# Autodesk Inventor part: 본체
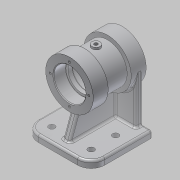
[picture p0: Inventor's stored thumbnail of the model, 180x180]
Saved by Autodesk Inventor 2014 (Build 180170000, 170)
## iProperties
Created: 2020-06
Part Number: 본체
Material: 알루미늄 6061
Document SubType Name: 판금
Designer: NET
Density: 2.71 g/cm^3
Appearance: 알루미늄 - 평지
Sheet Metal Rule: 기본값
Mass: 729.164 g
Surface Area: 648.266 cm^2
Volume: 269.064 cm^3
Author: NET
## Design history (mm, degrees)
sketch "스케치1"
  geometry: C1 r 29 at (0, 0); 1 further point
  constraints: 1 centre point, 1 coincident
  dimensions: "d0" = 58 diameter of C1
extrude "돌출1" new body sketch "스케치1" stored distance "d1" = 78; taper "d2" = 0 deg
node "작업 평면1"
sketch "스케치2"
  geometry: 1 further point
sketch "스케치3"
  geometry: L1 (-49, -51)-(49, -51); L2 (49, -51)-(49, 39); L3 (49, 39)-(-49, 39); L4 (-49, 39)-(-49, -51); L5 (29, 39)-(-29, 39) reference; L6 (-29, -39)-(29, -39) reference; L7 (29, 39)-(-29, 39) reference; 1 further point
  constraints: 8 end point, 2 parallel, 1 horizontal, 1 perpendicular, 1 point on line
  dimensions: "d4" = 49 distance from line of point (0, 0) L4; "d5" = 98 distance of L2.end L3.end; "d6" = 90 distance between parallel lines of L1 L3
extrude "돌출2" join sketch "스케치3" distance "d7" = 10; taper "d8" = 0 deg
sketch "스케치6"
  geometry: L1 (49, 39)-(-49, 39) reference; L2 (-35, 29)-(35, 29); L3 (35, 29)-(35, 39); L4 (35, 39)-(-35, 39); L5 (-35, 39)-(-35, 29); 2 further points
  constraints: 8 end point, 2 midpoint, 2 parallel, 1 horizontal, 1 perpendicular
  dimensions: "d22" = 70 distance between parallel lines of L3 L5; "d23" = 35 distance from line of point (0, 0) L5; "d24" = 10 distance between parallel lines of L2 L4
sketch "스케치7"
  geometry: C1 r 29 at (0, 0) reference; C2 r 35 at (0, 0)
  constraints: 1 centre point, 1 coincident
  dimensions: "d25" = 70 diameter of C2
extrude "돌출4" join sketch "스케치7" distance "d26" = 27; taper "d27" = 0 deg
sketch "스케치8"
  geometry: C1 r 29 at (0, 0) reference; C2 r 35 at (0, 0)
  constraints: 1 centre point, 1 coincident
  dimensions: "d28" = 70 diameter of C2
extrude "돌출5" join sketch "스케치8" distance "d29" = 22; taper "d30" = 0 deg
extrude "돌출6" join sketch "스케치6" stored distance "d31" = 22; taper "d32" = 0 deg
sketch "스케치10"
  geometry: C1 r 35 at (0, 0) reference; C2 r 23.5 at (0, 0)
  constraints: 1 centre point, 1 coincident
  dimensions: "d41" = 47 diameter of C2
extrude "돌출7" cut sketch "스케치10" distance "d42" = 18; taper "d43" = 0 deg
node "작업 평면3"
sketch "스케치19"
  geometry: L1 (49, 39)-(-49, 39) reference; C1 r 4.5 at (29, 5); C2 r 4.5 at (29, -31); C3 r 4.5 at (-29, 5); C4 r 4.5 at (-29, -31); 1 further point
  constraints: 4 centre point, 3 equal radius, 2 vertical alignment, 1 horizontal alignment
  dimensions: "d63" = 36 distance of C2.centre C1.centre; "d64" = 36 distance of C4.centre C3.centre; "d66" = 29 horizontal distance of point (0, 0) C2.centre; "d67" = 70 distance from line of C2.centre L1; "d68" = 58 distance of C4.centre C2.centre; "d69" = 9 diameter of C2
extrude "돌출13" cut sketch "스케치19" stored distance "d70" = 18; taper "d71" = 0 deg
sketch "스케치20"
  geometry: C1 r 23.5 at (0, 0) reference; C2 r 35 at (0, 0) reference; A1 r 28.5 centre (0, 0) between (0, 28.5) and (-28.5, 0); 2 further points
  constraints: 4 point on circle, 2 horizontal alignment, 2 vertical alignment, 1 centre point, 1 coincident
  dimensions: "d72" = 57 diameter of A1
hole "구멍1" sketch "스케치20" at (0, 28.5), (-28.5, 0), (0, -28.5), (28.5, 0) diameter "d73" = 3.242; stored, may be unused: countersink angle "d77" = 90 deg, drill point angle "d79" = 118 deg; dims "d74" = 10, "d75" = 4, "d76" = 2, "d78" = 12
sketch "스케치22"
  geometry: L1 (35, 70)-(35, 0) reference; C1 r 23.5 at (0, 0) reference; C2 r 35 at (0, 0); A1 r 35 centre (0, 0) between (-35, 0) and (35, 0) reference
  constraints: 1 centre point, 1 coincident, 1 tangent
extrude "돌출14" join sketch "스케치22" distance "d80" = 5; taper "d81" = 0 deg
sketch "스케치24"
  geometry: C1 r 35 at (0, 0); A1 r 29 centre (0, 0) between (-29, 0) and (-29, 0) reference
  constraints: 1 centre point, 1 coincident
extrude "돌출15" cut sketch "스케치24" distance "d82" = 5; taper "d83" = 0 deg
sketch "스케치28"
  geometry: C1 r 1.621 at (0, -28.5) reference; C2 r 1.621 at (0, 28.5) reference; C3 r 1.621 at (-28.5, 0) reference; C4 r 1.621 at (28.5, 0) reference; C5 r 23.5 at (0, 0) reference; C6 r 35 at (0, 0) reference; C7 r 35 at (0, 0)
  constraints: 1 centre point, 1 coincident, 1 concentric
extrude "돌출17" cut sketch "스케치28" distance "d87" = 5; taper "d88" = 0 deg
sketch "스케치31"
  geometry: C1 r 23.5 at (0, 0) reference; C2 r 35 at (0, 0) reference; A1 r 28.5 centre (0, 0) between (0, -28.5) and (28.5, 0); 2 further points
  constraints: 4 point on circle, 2 horizontal alignment, 2 vertical alignment, 1 centre point, 1 coincident
  dimensions: "d97" = 57 diameter of A1
hole "구멍2" sketch "스케치31" at (0, -28.5), (28.5, 0), (0, 28.5), (-28.5, 0) diameter "d98" = 3.242; stored, may be unused: countersink angle "d102" = 90 deg, drill point angle "d104" = 118 deg; dims "d99" = 10, "d100" = 4, "d101" = 2, "d103" = 12
node "작업 평면4"
sketch "스케치32"
  geometry: L1 (-23.5, 44)-(23.5, 44) reference; C1 r 6 at (0, 5); 1 further point
  constraints: 1 centre point, 1 vertical alignment
  dimensions: "d106" = 39 distance from line of C1.centre L1; "d107" = 12 diameter of C1
extrude "돌출18" join sketch "스케치32" stored distance "d108" = 5; taper "d109" = 0 deg
sketch "스케치33"
  geometry: C1 r 6 at (0, 0) reference; 1 further point
chamfer "모따기1" distance "d117" = 1; stored, may be unused: second distance "d118" = 2, angle "d119" = 45 deg
fillet "모깎기5" dims "d121" = 20
fillet "모깎기6" dims "d122" = 3
fillet "모깎기7" dims "d123" = 3
fillet "모깎기9" dims "d125" = 3
sketch "스케치34"
  geometry: L1 (0, 70)-(7, 70) reference; L2 (0, 70)-(0, 0) reference; 2 further points
  constraints: 1 other
  dimensions: "d126" = 4 distance from line of point (4, 25) L2; "d127" = 45 distance from line of point (4, 25) L1
feature "엠보싱1" sketch "스케치34" dims "d128" = 0.5, "d129" = 0
sketch "스케치36"
  geometry: C1 r 23.5 at (0, 0) reference; C2 r 23.5 at (0, 0)
  constraints: 1 centre point, 1 coincident, 1 concentric
extrude "돌출19" cut sketch "스케치36" distance "d130" = 5; taper "d131" = 0 deg
sketch "스케치37"
  geometry: C1 r 23.5 at (0, 0) reference; C2 r 23.5 at (0, 0)
  constraints: 1 centre point, 1 coincident, 1 concentric
extrude "돌출20" cut sketch "스케치37" distance "d133" = 13; taper "d134" = 0 deg
sketch "스케치38"
  geometry: C1 r 29 at (0, 0) reference; C2 r 29 at (0, 0)
  constraints: 1 centre point, 1 coincident, 1 concentric
extrude "돌출21" join sketch "스케치38" stored distance "d135" = 13; taper "d136" = 0 deg
sketch "스케치39"
  geometry: C1 r 23.5 at (0, 0) reference; C2 r 20 at (0, 0)
  constraints: 1 centre point, 1 coincident
  dimensions: "d137" = 40 diameter of C2
extrude "돌출22" cut sketch "스케치39" distance "d138" = 6; taper "d139" = 0 deg
sketch "스케치40"
  geometry: C1 r 23.5 at (0, 0) reference; C2 r 20 at (0, 0)
  constraints: 1 centre point, 1 coincident
  dimensions: "d140" = 40 diameter of C2
extrude "돌출23" cut sketch "스케치40" distance "d141" = 6; taper "d142" = 0 deg
sketch "스케치41"
  geometry: C1 r 20 at (0, 0) reference; C2 r 23 at (0, 0)
  constraints: 1 centre point, 1 coincident
  dimensions: "d143" = 46 diameter of C2
extrude "돌출24" cut sketch "스케치41" distance "d144" = 30; taper "d145" = 0 deg
fillet "모깎기10" dims "d146" = 0.3
fillet "모깎기11" dims "d147" = 3
sketch "스케치42"
  geometry: L1 (-31, -70)-(39, -70) reference; L2 (-35.5, -70)-(-26.5, -70) reference; L3 (-39, -70)-(-26.261, -35); L4 (-51, -80)-(-51, -73) reference; L5 (-34, -35)-(-12, -35) reference; 1 further point
  constraints: 2 end point, 2 point on line
  dimensions: "d148" = 12 distance from line of L3.start L4; "d149" = 70 deg angle of L1 L3
feature "리브4" sketch "스케치42" dims "d150" = 1, "d151" = 10, "d152" = 0, "d153" = 0, "d154" = 1, "d155" = 1
fillet "모깎기12" dims "d156" = 3
hole "구멍4" sketch "스케치33" diameter "d157" = 5.188; stored, may be unused: countersink angle "d161" = 90 deg, drill point angle "d163" = 118 deg; dims "d158" = 10, "d159" = 4, "d160" = 2, "d162" = 12
fillet "모깎기13" dims "d164" = 3
fillet "모깎기14" dims "d165" = 3
node "솔리드1"
node "투영된 루프1"
other parameters: "d59" = 32, "d105" = 32, "K계수" = 4.4, "BendRadius" = 0.5 (derived), "BendReliefWidth" = 0.5 (derived), "BendReliefDepth" = 0.25 (derived), "CornerReliefSize" = 2 (derived), "SeamGap" = 0.01, "MinimumRemnant" = 1 (derived), "TransitionRadius" = 0.5 (= BendRadius)
